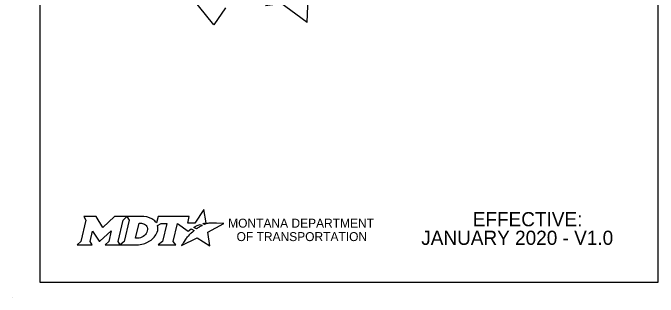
# Model space of a CAD drawing. Extents: x 49991.4 to 50021, y 49987.6 to 50011.4.
# Drawn here: x 49999.98 to 50008.61, y 49999.86 to 50003.67 of the extents above; entities that cross this region are included whole.
import ezdxf

# ---------------------------------------------------------------- set-up
doc = ezdxf.new("R2010")
doc.units = 0
doc.layers.add('Level 1', color=7, linetype='Continuous')
doc.layers.add('Level 2', color=7, linetype='Continuous')

msp = doc.modelspace()

# ---------------------------------------------------------------- linework, layer by layer
at = {"layer": 'Level 1'}
for p, q in [((50003.9141, 50003.5421), (50003.943, 50004.1524)), ((49999.9766, 49999.8624), (49999.9766, 49999.8624))]:
    msp.add_line(p, q, dxfattribs=at)
msp.add_lwpolyline([(50008.6146, 50011.2628), (50000.3356, 50011.2628), (50000.3356, 50000.0624), (50008.6146, 50000.0624)], close=True, dxfattribs=at)
for points in [[(50002.8213, 50003.7389), (50002.6664, 50003.5102), (50002.3685, 50003.8848)], [(50003.9141, 50003.5421), (50003.5444, 50003.8162), (50003.5193, 50003.7878), (50003.3563, 50003.7653)]]:
    msp.add_lwpolyline(points, dxfattribs=at)
at = {"layer": 'Level 2'}
for points in [[(50002.5398, 50000.8355), (50002.5191, 50000.8467), (50002.5424, 50000.8523), (50002.5657, 50000.8562), (50002.5308, 50001.0364), (50002.4118, 50000.8539), (50002.3173, 50000.8524), (50002.3379, 50000.9406), (50001.9195, 50000.9409), (50001.8992, 50000.8558), (50001.8875, 50000.8725)], [(50000.9258, 50000.9408), (50000.9539, 50000.8941), (50000.8871, 50000.6075), (50000.8356, 50000.5624), (50001.0388, 50000.5624), (50001.0118, 50000.608), (50001.0441, 50000.7482), (50001.1317, 50000.6102), (50001.1423, 50000.6102), (50001.2924, 50000.7492), (50001.2595, 50000.607), (50001.2102, 50000.5629), (50001.4134, 50000.5629), (50001.3858, 50000.6096), (50001.4522, 50000.8943)], [(50001.4522, 50000.8943), (50001.5028, 50000.9408), (50001.3381, 50000.9408), (50001.1789, 50000.7949), (50001.0897, 50000.9403), (50000.9258, 50000.9408)], [(50001.73, 50000.9408), (50001.5028, 50000.9408), (50001.5322, 50000.8951), (50001.4643, 50000.6075), (50001.4134, 50000.5629), (50001.6346, 50000.5629)], [(50001.7781, 50000.7674), (50001.7756, 50000.7512), (50001.7693, 50000.7327), (50001.7609, 50000.7163), (50001.7496, 50000.7012), (50001.7366, 50000.6875), (50001.7207, 50000.6749), (50001.7041, 50000.6654), (50001.686, 50000.6577), (50001.6678, 50000.6531), (50001.6494, 50000.6513), (50001.6177, 50000.6513), (50001.6649, 50000.8512), (50001.6967, 50000.8512), (50001.7121, 50000.8501), (50001.7272, 50000.8461), (50001.7404, 50000.8401), (50001.7526, 50000.8318), (50001.7622, 50000.8218), (50001.7696, 50000.8098), (50001.7751, 50000.7974), (50001.7781, 50000.7826), (50001.7782, 50000.7765), (50001.7781, 50000.7674)], [(50001.9127, 50000.8227), (50001.9621, 50000.8487), (50002.0359, 50000.8487), (50001.9787, 50000.6079), (50001.9236, 50000.5625), (50002.156, 50000.5625), (50002.1219, 50000.6081), (50002.1784, 50000.8486), (50002.321, 50000.7453), (50002.3633, 50000.7754), (50002.4027, 50000.7536)], [(50002.291, 50000.6417), (50002.2605, 50000.593), (50002.251, 50000.5779), (50002.2394, 50000.5608), (50002.2349, 50000.5522), (50002.4454, 50000.6584), (50002.6132, 50000.5483), (50002.587, 50000.7336), (50002.8008, 50000.8505), (50002.7023, 50000.8519), (50002.642, 50000.8529), (50002.6005, 50000.8535), (50002.5868, 50000.8504), (50002.5769, 50000.8479), (50002.5602, 50000.8434), (50002.5398, 50000.8355)], [(50002.439, 50000.7802), (50002.4343, 50000.7768), (50002.3977, 50000.796), (50002.4181, 50000.8075), (50002.4263, 50000.8119), (50002.4436, 50000.8198), (50002.4549, 50000.825), (50002.4707, 50000.8311), (50002.4855, 50000.8365), (50002.509, 50000.8216), (50002.5011, 50000.8174), (50002.4919, 50000.8125), (50002.4835, 50000.8081), (50002.4735, 50000.8023), (50002.4697, 50000.8001), (50002.4642, 50000.7968), (50002.4593, 50000.7939), (50002.4546, 50000.7908), (50002.4494, 50000.7872), (50002.4441, 50000.7836), (50002.439, 50000.7802)], [(50002.3188, 50000.674), (50002.3188, 50000.674)], [(50001.7261, 50000.5775), (50001.7428, 50000.5828), (50001.7687, 50000.5937), (50001.8096, 50000.6156)]]:
    msp.add_lwpolyline(points, dxfattribs=at)
for centre, radius, start, end in [((50001.7763, 50000.7839), 0.1419, 339.53292, 15.85821), ((50001.6881, 50000.8185), 0.2365, 300.91025, 339.13831)]:
    msp.add_arc(centre, radius, start, end, dxfattribs=at)
for centre, major_axis, ratio, start_param, end_param in [((50001.7258, 50000.846), (0.1669, -0.0074), 0.568097, 0.61298, 1.570796), ((50001.8371, 50000.8606), (0.0721, -0.059), 0.469099, 1.225588, 1.570796), ((50002.3803, 50000.7342), (-0.0223, -0.0195), 0.021651, 3.157348, 6.283185), ((50002.3049, 50000.6579), (-0.0139, -0.0161), 0.008222, 0, 3.137361), ((50002.3384, 50000.6943), (-0.0196, -0.0204), 0.016458, 3.141593, 6.279097), ((50001.6353, 50000.8596), (0, 0.2967), 0.987302, 3.139398, 3.456847)]:
    msp.add_ellipse(centre, major_axis=major_axis, ratio=ratio, start_param=start_param, end_param=end_param, dxfattribs=at)

# ---------------------------------------------------------------- texts
at = {"layer": 'Level 1'}
for s, p in [('EFFECTIVE:', (50006.133, 50000.8115)), ('JANUARY 2020 - V1.0', (50005.4434, 50000.5624))]:
    msp.add_text(s, height=0.19, dxfattribs=at).set_placement(p)
at = {"layer": 'Level 2'}
for s, p in [('MONTANA DEPARTMENT', (50002.8586, 50000.7931)), ('OF TRANSPORTATION', (50002.9714, 50000.6131))]:
    msp.add_text(s, height=0.12, dxfattribs=at).set_placement(p)

doc.saveas('drawing.dxf')
